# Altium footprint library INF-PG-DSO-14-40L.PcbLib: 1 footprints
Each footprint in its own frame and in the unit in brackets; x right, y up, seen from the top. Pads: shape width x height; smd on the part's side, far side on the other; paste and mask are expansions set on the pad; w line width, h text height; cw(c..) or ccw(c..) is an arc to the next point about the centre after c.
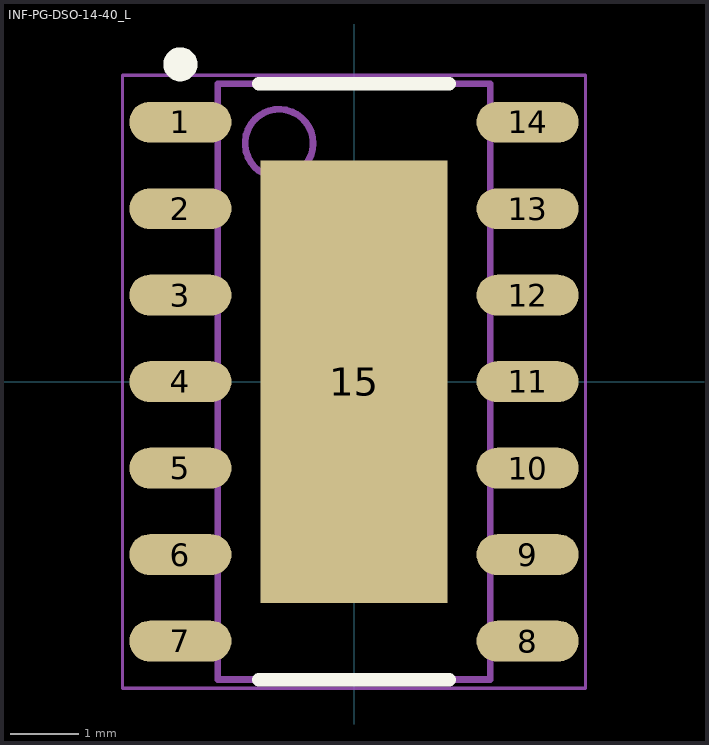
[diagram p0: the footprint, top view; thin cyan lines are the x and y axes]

## INF-PG-DSO-14-40_L [mm] "SOP, 14-Leads, Body 8.65x3.9mm, Pitch 1.27mm, Thermal Pad 6.5x2.75mm, IPC High Density"
height 1.7
pads (15):
  oval 1.5x0.6 smd: 1(-2.55,3.81) 2(-2.55,2.54) 3(-2.55,1.27) 4(-2.55,0) 5(-2.55,-1.27) 6(-2.55,-2.54) 7(-2.55,-3.81) 8(2.55,-3.81) 9(2.55,-2.54) 10(2.55,-1.27) 11(2.55,0) 12(2.55,1.27) 13(2.55,2.54) 14(2.55,3.81)
  rect 2.75x6.5 smd: 15(0,0)
Top Overlay:
  circle w0.25: c-2.55,4.66 r0.125
  lines w0.2: -1.4,-4.375 1.4,-4.375 ; -1.4,4.375 1.4,4.375
Mechanical 13:
  circle w0.1: c-1.1,3.5 r0.5
  lines w0.1: -2,-4.375 2,-4.375 2,4.375 -2,4.375 -2,-4.375
Mechanical 15:
  lines w0.05: -3.4,-4.5 3.4,-4.5 3.4,4.5 -3.4,4.5 -3.4,-4.5
  lines w0.1: -0.5,0 0.5,0 ; 0,-0.5 0,0.5
3D body: height 1.7, standoff 0, extent -2,-4.375 2,4.375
